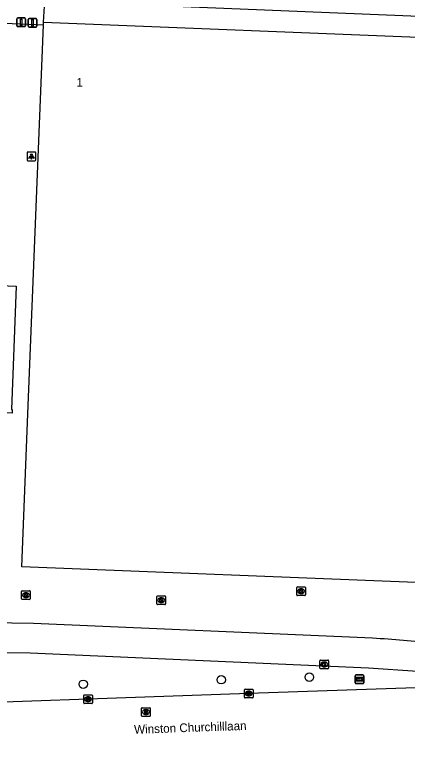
# Model space of a CAD drawing. Extents: x 160891 to 161384, y 386490 to 386907.
# Drawn here: x 161265.4 to 161310.5, y 386500.4 to 386584.8 of the extents above; entities that cross this region are included whole.
import ezdxf

# ---------------------------------------------------------------- set-up
doc = ezdxf.new("R2010")
doc.units = 0
for name, color, linetype in [('IMGEO_Afsluitpaal', 7, 'Continuous'), ('IMGEO_Boom', 7, 'Continuous'), ('IMGEO_Fietspad_gesloten', 7, 'Continuous'), ('IMGEO_Kolk', 7, 'Continuous'), ('IMGEO_Lichtpunt', 7, 'Continuous'), ('IMGEO_Openbare_ruimte_label', 7, 'Continuous'), ('IMGEO_Pand', 7, 'Continuous'), ('IMGEO_Pand_nummerreeks', 7, 'Continuous'), ('IMGEO_Rijbaan_regionaal_gesloten', 7, 'Continuous'), ('IMGEO_Rioolput', 7, 'Continuous'), ('IMGEO_Voetpad_open', 7, 'Continuous'), ('IMGEO_Wegwijzer', 7, 'Continuous')]:
    doc.layers.add(name, color=color, linetype=linetype)

msp = doc.modelspace()

# ---------------------------------------------------------------- linework, layer by layer
at = {"layer": 'IMGEO_Afsluitpaal'}
for p, q in [((161265.659, 386583.512), (161265.659, 386584.312)), ((161265.659, 386584.312), (161265.659, 386583.512)), ((161265.759, 386584.412), (161266.549, 386584.412)), ((161266.549, 386584.412), (161265.759, 386584.412)), ((161266.649, 386584.312), (161266.649, 386583.512)), ((161266.649, 386583.512), (161266.649, 386584.312)), ((161266.966, 386583.45), (161266.966, 386584.25)), ((161266.966, 386584.25), (161266.966, 386583.45)), ((161267.066, 386584.35), (161267.856, 386584.35)), ((161267.856, 386584.35), (161267.066, 386584.35)), ((161267.956, 386584.25), (161267.956, 386583.45)), ((161267.956, 386583.45), (161267.956, 386584.25)), ((161266.549, 386583.412), (161265.759, 386583.412)), ((161265.759, 386583.412), (161266.549, 386583.412)), ((161267.856, 386583.35), (161267.066, 386583.35)), ((161267.066, 386583.35), (161267.856, 386583.35))]:
    msp.add_line(p, q, dxfattribs=at)
for points in [[(161266.079, 386584.287), (161266.229, 386584.287), (161266.229, 386583.537), (161266.079, 386583.537), (161266.079, 386584.287)], [(161267.386, 386584.225), (161267.536, 386584.225), (161267.536, 386583.475), (161267.386, 386583.475), (161267.386, 386584.225)]]:
    msp.add_lwpolyline(points, dxfattribs=at)
for centre, start, end in [((161265.759, 386584.312), 90, 180), ((161265.759, 386584.312), 90, 180), ((161266.549, 386584.312), 0, 90), ((161266.549, 386584.312), 360, 90), ((161267.066, 386584.25), 90, 180), ((161267.066, 386584.25), 90, 180), ((161267.856, 386584.25), 0, 90), ((161267.856, 386584.25), 360, 90), ((161265.759, 386583.512), 180, 270), ((161265.759, 386583.512), 180, 270), ((161266.549, 386583.512), 270, 0), ((161266.549, 386583.512), 270, 0), ((161267.066, 386583.45), 180, 270), ((161267.066, 386583.45), 180, 270), ((161267.856, 386583.45), 270, 0), ((161267.856, 386583.45), 270, 0)]:
    msp.add_arc(centre, 0.1, start, end, dxfattribs=at)
at = {"layer": 'IMGEO_Boom'}
for centre in [(161289.154, 386508.292), (161299.276, 386508.593), (161273.292, 386507.765)]:
    msp.add_circle(centre, 0.489, dxfattribs=at)
at = {"layer": 'IMGEO_Fietspad_gesloten'}
for points in [[(161268.851, 386586.379), (161314.691, 386584.489), (161334.635, 386583.706)], [(161306.554, 386513.058), (161267.578, 386514.754), (161262.551, 386514.831), (161253.325, 386514.853), (161253.233, 386514.853)], [(161109.839, 386506.955), (161116.836, 386508.035), (161123.035, 386508.931), (161127.225, 386509.29), (161167.964, 386510.348), (161215.734, 386511.569), (161215.758, 386511.159), (161222.805, 386511.284), (161237.753, 386511.488), (161259.697, 386511.429), (161267.164, 386511.376), (161306.097, 386509.668), (161311.73, 386509.285), (161311.776, 386509.705), (161313.071, 386509.592)]]:
    msp.add_lwpolyline(points, dxfattribs=at)
msp.add_arc((161302.973, 386437.113), 76.029, 81.96498, 87.30019, dxfattribs=at)
at = {"layer": 'IMGEO_Kolk'}
for p, q in [((161297.827, 386518.043), (161297.827, 386518.895)), ((161297.902, 386518.969), (161298.754, 386518.969)), ((161298.828, 386518.895), (161298.828, 386518.043)), ((161266.193, 386517.596), (161266.193, 386518.448)), ((161266.268, 386518.522), (161267.12, 386518.522)), ((161266.681, 386518.302), (161266.706, 386518.302)), ((161267.194, 386518.448), (161267.194, 386517.596)), ((161298.338, 386518.189), (161298.313, 386518.189)), ((161298.315, 386518.749), (161298.34, 386518.749)), ((161267.12, 386517.522), (161266.268, 386517.522)), ((161266.704, 386517.742), (161266.679, 386517.742)), ((161281.749, 386517.013), (161281.749, 386517.865)), ((161281.824, 386517.939), (161282.676, 386517.939)), ((161282.26, 386517.159), (161282.235, 386517.159)), ((161282.237, 386517.719), (161282.262, 386517.719)), ((161282.75, 386517.865), (161282.75, 386517.013)), ((161298.754, 386517.969), (161297.902, 386517.969)), ((161282.676, 386516.939), (161281.824, 386516.939)), ((161300.484, 386509.627), (161300.484, 386510.479)), ((161300.559, 386510.553), (161301.411, 386510.553)), ((161301.485, 386510.479), (161301.485, 386509.627)), ((161301.411, 386509.553), (161300.559, 386509.553)), ((161300.995, 386509.773), (161300.97, 386509.773)), ((161300.972, 386510.333), (161300.997, 386510.333)), ((161291.805, 386506.274), (161291.805, 386507.126)), ((161291.88, 386507.2), (161292.732, 386507.2)), ((161292.806, 386507.126), (161292.806, 386506.274)), ((161273.332, 386505.622), (161273.332, 386506.474)), ((161273.407, 386506.548), (161274.259, 386506.548)), ((161273.82, 386506.328), (161273.845, 386506.328)), ((161274.333, 386506.474), (161274.333, 386505.622)), ((161292.732, 386506.2), (161291.88, 386506.2)), ((161292.316, 386506.42), (161292.291, 386506.42)), ((161292.293, 386506.98), (161292.318, 386506.98)), ((161274.259, 386505.548), (161273.407, 386505.548)), ((161273.843, 386505.768), (161273.818, 386505.768))]:
    msp.add_line(p, q, dxfattribs=at)
for points in [[(161297.827, 386518.043), (161297.827, 386518.895)], [(161297.902, 386518.969), (161298.754, 386518.969)], [(161298.828, 386518.895), (161298.828, 386518.043)], [(161266.193, 386517.596), (161266.193, 386518.448)], [(161266.268, 386518.522), (161267.12, 386518.522)], [(161266.514, 386518.222), (161266.637, 386518.222), (161266.637, 386518.071), (161266.767, 386518.222), (161266.931, 386518.222), (161266.785, 386518.071), (161266.938, 386517.822), (161266.786, 386517.822), (161266.701, 386517.986), (161266.637, 386517.919), (161266.637, 386517.822), (161266.514, 386517.822), (161266.514, 386518.222)], [(161267.194, 386518.448), (161267.194, 386517.596)], [(161298.148, 386518.669), (161298.271, 386518.669), (161298.271, 386518.518), (161298.401, 386518.669), (161298.565, 386518.669), (161298.419, 386518.518), (161298.572, 386518.269), (161298.42, 386518.269), (161298.335, 386518.433), (161298.271, 386518.366), (161298.271, 386518.269), (161298.148, 386518.269), (161298.148, 386518.669)], [(161267.12, 386517.522), (161266.268, 386517.522)], [(161281.749, 386517.013), (161281.749, 386517.865)], [(161281.824, 386517.939), (161282.676, 386517.939)], [(161282.07, 386517.639), (161282.193, 386517.639), (161282.193, 386517.488), (161282.323, 386517.639), (161282.487, 386517.639), (161282.341, 386517.488), (161282.494, 386517.239), (161282.342, 386517.239), (161282.257, 386517.403), (161282.193, 386517.336), (161282.193, 386517.239), (161282.07, 386517.239), (161282.07, 386517.639)], [(161282.75, 386517.865), (161282.75, 386517.013)], [(161298.754, 386517.969), (161297.902, 386517.969)], [(161282.676, 386516.939), (161281.824, 386516.939)], [(161300.484, 386509.627), (161300.484, 386510.479)], [(161300.559, 386510.553), (161301.411, 386510.553)], [(161301.485, 386510.479), (161301.485, 386509.627)], [(161301.411, 386509.553), (161300.559, 386509.553)], [(161300.805, 386510.253), (161300.928, 386510.253), (161300.928, 386510.102), (161301.058, 386510.253), (161301.222, 386510.253), (161301.076, 386510.102), (161301.229, 386509.853), (161301.077, 386509.853), (161300.992, 386510.017), (161300.928, 386509.95), (161300.928, 386509.853), (161300.805, 386509.853), (161300.805, 386510.253)], [(161291.805, 386506.274), (161291.805, 386507.126)], [(161291.88, 386507.2), (161292.732, 386507.2)], [(161292.806, 386507.126), (161292.806, 386506.274)], [(161273.332, 386505.622), (161273.332, 386506.474)], [(161273.407, 386506.548), (161274.259, 386506.548)], [(161273.653, 386506.248), (161273.776, 386506.248), (161273.776, 386506.097), (161273.906, 386506.248), (161274.07, 386506.248), (161273.924, 386506.097), (161274.077, 386505.848), (161273.925, 386505.848), (161273.84, 386506.012), (161273.776, 386505.945), (161273.776, 386505.848), (161273.653, 386505.848), (161273.653, 386506.248)], [(161274.333, 386506.474), (161274.333, 386505.622)], [(161292.732, 386506.2), (161291.88, 386506.2)], [(161292.126, 386506.9), (161292.249, 386506.9), (161292.249, 386506.749), (161292.379, 386506.9), (161292.543, 386506.9), (161292.397, 386506.749), (161292.55, 386506.5), (161292.398, 386506.5), (161292.313, 386506.664), (161292.249, 386506.597), (161292.249, 386506.5), (161292.126, 386506.5), (161292.126, 386506.9)], [(161274.259, 386505.548), (161273.407, 386505.548)]]:
    msp.add_lwpolyline(points, dxfattribs=at)
for centre, start, end in [((161297.904, 386518.893), 91.55205, 178.44795), ((161297.904, 386518.893), 91.55205, 178.44795), ((161298.752, 386518.893), 1.55205, 88.44795), ((161298.752, 386518.893), 1.55205, 88.44795), ((161266.27, 386518.446), 91.55205, 178.44795), ((161266.27, 386518.446), 91.55205, 178.44795), ((161267.118, 386518.446), 1.55205, 88.44795), ((161267.118, 386518.446), 1.55205, 88.44795), ((161297.904, 386518.045), 181.55205, 268.44795), ((161297.904, 386518.045), 181.55205, 268.44795), ((161298.752, 386518.045), 271.55205, 358.44795), ((161298.752, 386518.045), 271.55205, 358.44795), ((161266.27, 386517.598), 181.55205, 268.44795), ((161266.27, 386517.598), 181.55205, 268.44795), ((161267.118, 386517.598), 271.55205, 358.44795), ((161267.118, 386517.598), 271.55205, 358.44795), ((161281.826, 386517.863), 91.55205, 178.44795), ((161281.826, 386517.863), 91.55205, 178.44795), ((161282.674, 386517.863), 1.55205, 88.44795), ((161282.674, 386517.863), 1.55205, 88.44795), ((161281.826, 386517.015), 181.55205, 268.44795), ((161281.826, 386517.015), 181.55205, 268.44795), ((161282.674, 386517.015), 271.55205, 358.44795), ((161282.674, 386517.015), 271.55205, 358.44795), ((161300.561, 386510.477), 91.55205, 178.44795), ((161300.561, 386510.477), 91.55205, 178.44795), ((161301.409, 386510.477), 1.55205, 88.44795), ((161301.409, 386510.477), 1.55205, 88.44795), ((161300.561, 386509.629), 181.55205, 268.44795), ((161300.561, 386509.629), 181.55205, 268.44795), ((161301.409, 386509.629), 271.55205, 358.44795), ((161301.409, 386509.629), 271.55205, 358.44795), ((161291.882, 386507.124), 91.55205, 178.44795), ((161291.882, 386507.124), 91.55205, 178.44795), ((161292.73, 386507.124), 1.55205, 88.44795), ((161292.73, 386507.124), 1.55205, 88.44795), ((161273.409, 386506.472), 91.55205, 178.44795), ((161273.409, 386506.472), 91.55205, 178.44795), ((161274.257, 386506.472), 1.55205, 88.44795), ((161274.257, 386506.472), 1.55205, 88.44795), ((161291.882, 386506.276), 181.55205, 268.44795), ((161291.882, 386506.276), 181.55205, 268.44795), ((161292.73, 386506.276), 271.55205, 358.44795), ((161292.73, 386506.276), 271.55205, 358.44795), ((161273.409, 386505.624), 181.55205, 268.44795), ((161273.409, 386505.624), 181.55205, 268.44795), ((161274.257, 386505.624), 271.55205, 358.44795), ((161274.257, 386505.624), 271.55205, 358.44795)]:
    msp.add_arc(centre, 0.0765, start, end, dxfattribs=at)
for centre, major_axis, ratio, start_param, end_param in [((161266.68, 386518.022), (-0.387, 0.002), 0.722429, 4.712389, 7.853982), ((161266.705, 386518.022), (-0.39, 0.002), 0.717154, 1.570796, 4.712389), ((161298.314, 386518.469), (-0.387, 0.002), 0.722429, 4.712389, 7.853982), ((161298.339, 386518.469), (-0.39, 0.002), 0.717154, 1.570796, 4.712389), ((161282.236, 386517.439), (-0.387, 0.002), 0.722429, 4.712389, 7.853982), ((161282.261, 386517.439), (-0.39, 0.002), 0.717154, 1.570796, 4.712389), ((161300.971, 386510.053), (-0.387, 0.002), 0.722429, 4.712389, 7.853982), ((161300.996, 386510.053), (-0.39, 0.002), 0.717154, 1.570796, 4.712389), ((161273.819, 386506.048), (-0.387, 0.002), 0.722429, 4.712389, 7.853982), ((161273.844, 386506.048), (-0.39, 0.002), 0.717154, 1.570796, 4.712389), ((161292.292, 386506.7), (-0.387, 0.002), 0.722429, 4.712389, 7.853982), ((161292.317, 386506.7), (-0.39, 0.002), 0.717154, 1.570796, 4.712389)]:
    msp.add_ellipse(centre, major_axis=major_axis, ratio=ratio, start_param=start_param, end_param=end_param, dxfattribs=at)
at = {"layer": 'IMGEO_Lichtpunt'}
for p, q in [((161266.825, 386568.889), (161266.825, 386568.082)), ((161266.825, 386568.889), (161266.825, 386568.082)), ((161267.727, 386568.984), (161266.919, 386568.984)), ((161267.727, 386568.984), (161266.919, 386568.984)), ((161267.821, 386568.082), (161267.821, 386568.889)), ((161267.821, 386568.082), (161267.821, 386568.889)), ((161266.919, 386567.988), (161267.727, 386567.988)), ((161266.919, 386567.988), (161267.727, 386567.988))]:
    msp.add_line(p, q, dxfattribs=at)
for points in [[(161267.199, 386568.553), (161267.238, 386568.525), (161267.05, 386568.263), (161267.012, 386568.29), (161267.199, 386568.553)], [(161267.301, 386568.505), (161267.348, 386568.505), (161267.348, 386568.183), (161267.301, 386568.183), (161267.301, 386568.505)], [(161267.411, 386568.525), (161267.449, 386568.552), (161267.636, 386568.29), (161267.597, 386568.262), (161267.411, 386568.525)]]:
    msp.add_lwpolyline(points, dxfattribs=at)
msp.add_circle((161267.324, 386568.687), 0.0994, dxfattribs=at)
for centre, start, end in [((161266.919, 386568.889), 90, 180), ((161266.919, 386568.889), 90, 180), ((161267.727, 386568.889), 0, 90), ((161267.727, 386568.889), 0, 90), ((161266.919, 386568.082), 180, 270), ((161266.919, 386568.082), 180, 270), ((161267.727, 386568.082), 270, 0), ((161267.727, 386568.082), 270, 360)]:
    msp.add_arc(centre, 0.0946, start, end, dxfattribs=at)
at = {"layer": 'IMGEO_Pand'}
for points in [[(161268.72, 386583.63), (161268.731, 386583.909)], [(161268.731, 386583.909), (161314.673, 386582.068)], [(161312.482, 386519.44), (161266.24, 386521.293), (161266.93, 386538.864), (161267.527, 386554.088), (161267.603, 386555.978), (161268.72, 386583.63)], [(161202.016, 386541.511), (161183.318, 386542.275), (161183.23, 386540.097), (161161.956, 386540.961), (161144.595, 386541.66), (161143.172, 386541.779), (161142.962, 386541.796), (161141.573, 386541.866), (161142.239, 386558.637), (161198.944, 386556.36), (161203.171, 386556.182), (161204.222, 386556.138), (161265.583, 386553.546), (161265.022, 386539.386), (161265.122, 386539.382), (161265.105, 386538.962), (161255.052, 386539.373), (161255.062, 386539.613), (161240.655, 386540.207), (161240.646, 386539.967), (161226.27, 386540.547), (161207.362, 386541.287)]]:
    msp.add_lwpolyline(points, dxfattribs=at)
at = {"layer": 'IMGEO_Rijbaan_regionaal_gesloten'}
msp.add_lwpolyline([(161323.08, 386507.769), (161322.733, 386507.751), (161292.306, 386506.7), (161273.833, 386506.048), (161254.372, 386505.373), (161233.906, 386504.66), (161214.429, 386503.969), (161194.971, 386503.319), (161175.497, 386502.675), (161154.024, 386501.918), (161133.563, 386501.204), (161132.874, 386501.189), (161113.106, 386500.507), (161110.084, 386500.399)], dxfattribs=at)
at = {"layer": 'IMGEO_Rioolput'}
for p, q in [((161279.993, 386504.148), (161279.993, 386505)), ((161280.068, 386505.074), (161280.92, 386505.074)), ((161280.481, 386504.854), (161280.506, 386504.854)), ((161280.994, 386505), (161280.994, 386504.148)), ((161280.92, 386504.074), (161280.068, 386504.074)), ((161280.504, 386504.294), (161280.479, 386504.294))]:
    msp.add_line(p, q, dxfattribs=at)
for points in [[(161279.993, 386504.148), (161279.993, 386505)], [(161280.068, 386505.074), (161280.92, 386505.074)], [(161280.582, 386504.772), (161280.33, 386504.774), (161280.33, 386504.374)], [(161280.33, 386504.374), (161280.454, 386504.374), (161280.454, 386504.536), (161280.465, 386504.536)], [(161280.508, 386504.693), (161280.454, 386504.693), (161280.454, 386504.612)], [(161280.454, 386504.612), (161280.506, 386504.612)], [(161280.512, 386504.507), (161280.583, 386504.374), (161280.723, 386504.374), (161280.658, 386504.5)], [(161280.994, 386505), (161280.994, 386504.148)], [(161280.92, 386504.074), (161280.068, 386504.074)]]:
    msp.add_lwpolyline(points, dxfattribs=at)
for centre, radius, start, end in [((161280.07, 386504.998), 0.0765, 91.55205, 178.44795), ((161280.07, 386504.998), 0.0765, 91.55205, 178.44795), ((161280.464, 386504.483), 0.0533, 26.02933, 88.69889), ((161280.49, 386504.801), 0.19, 274.7715, 282.96867), ((161280.514, 386504.597), 0.0964, 77.00612, 93.18647), ((161280.528, 386504.654), 0.0378, 276.66336, 79.67722), ((161280.581, 386504.662), 0.109, 350.36119, 89.41601), ((161280.579, 386504.662), 0.112, 277.58423, 350.98172), ((161280.563, 386504.447), 0.108, 29.51342, 73.79051), ((161280.918, 386504.998), 0.0765, 1.55205, 88.44795), ((161280.918, 386504.998), 0.0765, 1.55205, 88.44795), ((161280.07, 386504.15), 0.0765, 181.55205, 268.44795), ((161280.07, 386504.15), 0.0765, 181.55205, 268.44795), ((161280.918, 386504.15), 0.0765, 271.55205, 358.44795), ((161280.918, 386504.15), 0.0765, 271.55205, 358.44795)]:
    msp.add_arc(centre, radius, start, end, dxfattribs=at)
for centre, major_axis, ratio, start_param, end_param in [((161280.48, 386504.574), (-0.387, 0.002), 0.722429, 4.712389, 7.853982), ((161280.505, 386504.574), (-0.39, 0.002), 0.717154, 1.570796, 4.712389)]:
    msp.add_ellipse(centre, major_axis=major_axis, ratio=ratio, start_param=start_param, end_param=end_param, dxfattribs=at)
at = {"layer": 'IMGEO_Voetpad_open'}
for points in [[(161268.731, 386583.909), (161268.851, 386586.379)], [(161260.37, 386584.548), (161260.6, 386584.535), (161260.57, 386583.97), (161268.72, 386583.63)]]:
    msp.add_lwpolyline(points, dxfattribs=at)
at = {"layer": 'IMGEO_Wegwijzer'}
for p, q in [((161304.541, 386507.944), (161304.541, 386508.744)), ((161304.541, 386508.744), (161304.541, 386507.944)), ((161304.641, 386508.844), (161305.431, 386508.844)), ((161305.431, 386508.844), (161304.641, 386508.844)), ((161305.531, 386508.744), (161305.531, 386507.944)), ((161305.531, 386507.944), (161305.531, 386508.744)), ((161305.431, 386507.844), (161304.641, 386507.844)), ((161304.641, 386507.844), (161305.431, 386507.844))]:
    msp.add_line(p, q, dxfattribs=at)
for points in [[(161304.642, 386508.576), (161305.43, 386508.576), (161305.43, 386508.112), (161304.642, 386508.112), (161304.642, 386508.576)], [(161304.707, 386508.428), (161304.707, 386508.344), (161304.707, 386508.26), (161305.118, 386508.26), (161305.118, 386508.177), (161305.365, 386508.344), (161305.118, 386508.511), (161305.118, 386508.428), (161304.707, 386508.428)]]:
    msp.add_lwpolyline(points, dxfattribs=at)
for centre, start, end in [((161304.641, 386508.744), 90, 180), ((161304.641, 386508.744), 90, 180), ((161305.431, 386508.744), 0, 90), ((161305.431, 386508.744), 360, 90), ((161304.641, 386507.944), 180, 270), ((161304.641, 386507.944), 180, 270), ((161305.431, 386507.944), 270, 0), ((161305.431, 386507.944), 270, 0)]:
    msp.add_arc(centre, 0.1, start, end, dxfattribs=at)

# ---------------------------------------------------------------- texts
at = {"layer": 'IMGEO_Openbare_ruimte_label'}
msp.add_text('Winston Churchilllaan', height=1, rotation=2.00654, dxfattribs=at).set_placement((161279.148, 386502.065))
at = {"layer": 'IMGEO_Pand_nummerreeks'}
msp.add_text('1', height=1, dxfattribs=at).set_placement((161272.508, 386576.511))

doc.saveas('drawing.dxf')
